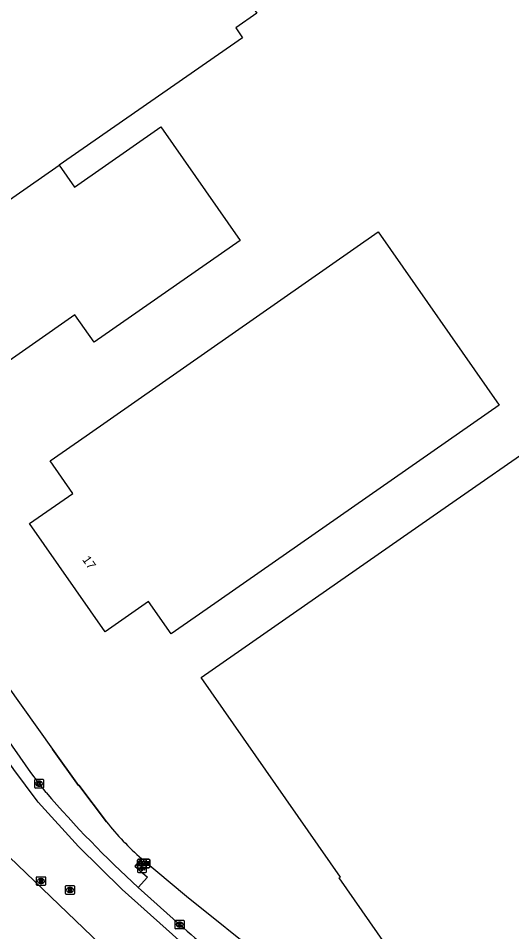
# Model space of a CAD drawing. Extents: x 156651 to 158072, y 387631 to 388990.
# Drawn here: x 157290.6 to 157346.7, y 388103.6 to 388207.5 of the extents above; entities that cross this region are included whole.
import ezdxf

# ---------------------------------------------------------------- set-up
doc = ezdxf.new("R2010")
doc.units = 0
for name, color, linetype in [('IMGEO_Berm_groen', 7, 'Continuous'), ('IMGEO_Hek', 7, 'Continuous'), ('IMGEO_Kolk', 7, 'Continuous'), ('IMGEO_Lichtpunt', 7, 'Continuous'), ('IMGEO_Pand', 7, 'Continuous'), ('IMGEO_Pand_nummerreeks', 7, 'Continuous'), ('IMGEO_Rijbaan_lokaal_gesloten', 7, 'Continuous'), ('IMGEO_Rijbaan_lokaal_open', 7, 'Continuous'), ('IMGEO_Rioolput', 7, 'Continuous'), ('IMGEO_Straatnaambord', 7, 'Continuous'), ('IMGEO_Verklikker', 7, 'Continuous')]:
    doc.layers.add(name, color=color, linetype=linetype)

msp = doc.modelspace()

# ---------------------------------------------------------------- linework, layer by layer
at = {"layer": 'IMGEO_Berm_groen'}
msp.add_lwpolyline([(157304.59, 388111.93), (157309.7, 388107.67), (157345.6, 388078.86), (157350.28, 388079.61), (157353.24, 388083.25)], dxfattribs=at)
at = {"layer": 'IMGEO_Hek'}
for points in [[(157297.47, 388120.3), (157297.41, 388120.27), (157294.46, 388124.39)], [(157300.61, 388116.11), (157297.47, 388120.3)], [(157304.59, 388111.93), (157309.7, 388107.67), (157345.6, 388078.86), (157350.28, 388079.61), (157353.24, 388083.25)]]:
    msp.add_lwpolyline(points, dxfattribs=at)
msp.add_arc((157325.46, 388135.8), 31.7, 218.3759, 228.8332, dxfattribs=at)
at = {"layer": 'IMGEO_Kolk'}
for p, q in [((157292.44, 388120.03), (157292.44, 388120.88)), ((157292.52, 388120.96), (157293.37, 388120.96)), ((157292.93, 388120.74), (157292.96, 388120.74)), ((157293.44, 388120.88), (157293.44, 388120.03)), ((157293.37, 388119.96), (157292.52, 388119.96)), ((157292.95, 388120.18), (157292.93, 388120.18)), ((157308.42, 388104), (157308.42, 388104.85)), ((157308.49, 388104.93), (157309.35, 388104.93)), ((157308.93, 388104.15), (157308.9, 388104.15)), ((157308.91, 388104.71), (157308.93, 388104.71)), ((157309.42, 388104.85), (157309.42, 388104)), ((157309.35, 388103.93), (157308.49, 388103.93))]:
    msp.add_line(p, q, dxfattribs=at)
for points in [[(157292.44, 388120.03), (157292.44, 388120.88)], [(157292.52, 388120.96), (157293.37, 388120.96)], [(157293.44, 388120.88), (157293.44, 388120.03)], [(157293.37, 388119.96), (157292.52, 388119.96)], [(157292.76, 388120.66), (157292.89, 388120.66), (157292.89, 388120.51), (157293.02, 388120.66), (157293.18, 388120.66), (157293.03, 388120.51), (157293.19, 388120.26), (157293.03, 388120.26), (157292.95, 388120.42), (157292.89, 388120.36), (157292.89, 388120.26), (157292.76, 388120.26), (157292.76, 388120.66)], [(157308.42, 388104), (157308.42, 388104.85)], [(157308.49, 388104.93), (157309.35, 388104.93)], [(157308.74, 388104.63), (157308.86, 388104.63), (157308.86, 388104.47), (157308.99, 388104.63), (157309.16, 388104.63), (157309.01, 388104.48), (157309.16, 388104.23), (157309.01, 388104.23), (157308.93, 388104.39), (157308.86, 388104.32), (157308.86, 388104.23), (157308.74, 388104.23), (157308.74, 388104.63)], [(157309.42, 388104.85), (157309.42, 388104)], [(157309.35, 388103.93), (157308.49, 388103.93)]]:
    msp.add_lwpolyline(points, dxfattribs=at)
for centre, start, end in [((157292.52, 388120.88), 91.552, 178.448), ((157292.52, 388120.88), 91.552, 178.448), ((157293.37, 388120.88), 1.552, 88.448), ((157293.37, 388120.88), 1.552, 88.448), ((157292.52, 388120.03), 181.552, 268.448), ((157292.52, 388120.03), 181.552, 268.448), ((157293.37, 388120.03), 271.552, 358.448), ((157293.37, 388120.03), 271.552, 358.448), ((157308.5, 388104.85), 91.552, 178.448), ((157308.5, 388104.85), 91.552, 178.448), ((157309.34, 388104.85), 1.552, 88.448), ((157309.34, 388104.85), 1.552, 88.448), ((157308.5, 388104), 181.552, 268.448), ((157308.5, 388104), 181.552, 268.448), ((157309.34, 388104), 271.552, 358.448), ((157309.34, 388104), 271.552, 358.448)]:
    msp.add_arc(centre, 0.0765, start, end, dxfattribs=at)
for centre, major_axis, ratio, start_param, end_param in [((157292.93, 388120.46), (-0.387, 0.002), 0.722429, 4.712389, 7.853982), ((157292.95, 388120.46), (-0.39, 0.002), 0.717154, 1.570796, 4.712389), ((157308.91, 388104.43), (-0.387, 0.002), 0.722429, 4.712389, 7.853982), ((157308.93, 388104.43), (-0.39, 0.002), 0.717154, 1.570796, 4.712389)]:
    msp.add_ellipse(centre, major_axis=major_axis, ratio=ratio, start_param=start_param, end_param=end_param, dxfattribs=at)
at = {"layer": 'IMGEO_Lichtpunt'}
for p, q in [((157305.05, 388111.35), (157304.24, 388111.35)), ((157305.05, 388111.35), (157304.24, 388111.35)), ((157304.14, 388111.26), (157304.14, 388110.45)), ((157304.14, 388111.26), (157304.14, 388110.45)), ((157304.24, 388110.36), (157305.05, 388110.36)), ((157304.24, 388110.36), (157305.05, 388110.36)), ((157305.14, 388110.45), (157305.14, 388111.26)), ((157305.14, 388110.45), (157305.14, 388111.26))]:
    msp.add_line(p, q, dxfattribs=at)
for points in [[(157304.52, 388110.92), (157304.56, 388110.89), (157304.37, 388110.63), (157304.33, 388110.66), (157304.52, 388110.92)], [(157304.62, 388110.87), (157304.67, 388110.87), (157304.67, 388110.55), (157304.62, 388110.55), (157304.62, 388110.87)], [(157304.73, 388110.89), (157304.77, 388110.92), (157304.96, 388110.66), (157304.92, 388110.63), (157304.73, 388110.89)]]:
    msp.add_lwpolyline(points, dxfattribs=at)
msp.add_circle((157304.64, 388111.06), 0.0994, dxfattribs=at)
for centre, start, end in [((157304.24, 388111.26), 90, 180), ((157304.24, 388111.26), 90, 180), ((157305.05, 388111.26), 0, 90), ((157305.05, 388111.26), 0, 90), ((157304.24, 388110.45), 180, 270), ((157304.24, 388110.45), 180, 270), ((157305.05, 388110.45), 270, 0), ((157305.05, 388110.45), 270, 360)]:
    msp.add_arc(centre, 0.0946, start, end, dxfattribs=at)
at = {"layer": 'IMGEO_Pand'}
for points in [[(157261.99, 388189.49), (157266.09, 388192.36), (157305.78, 388220.06), (157307.1, 388218.17), (157309.5, 388219.83), (157317.68, 388208.11), (157315.29, 388206.44), (157316.06, 388205.33), (157295.22, 388190.82)], [(157295.22, 388190.82), (157296.95, 388188.34), (157306.79, 388195.19), (157315.81, 388182.24), (157299.2, 388170.68), (157297.02, 388173.8), (157287.35, 388167.04), (157283.26, 388164.17), (157277.84, 388168.99)], [(157285.04, 388183.72), (157295.22, 388190.82)], [(157331.5, 388183.23), (157345.24, 388163.54), (157312.05, 388140.36), (157307.95, 388137.49), (157305.37, 388141.18), (157300.46, 388137.75), (157291.86, 388150.06), (157296.77, 388153.49), (157294.19, 388157.18), (157298.29, 388160.04), (157331.5, 388183.23)], [(157351.14, 388160.27), (157367.37, 388137.05), (157375.03, 388126.08), (157374.88, 388125.98), (157371, 388123.28), (157373.93, 388119.07), (157374.29, 388118.55), (157359.45, 388108.2), (157357.92, 388110.39), (157354.88, 388108.29), (157356.43, 388106.06), (157338.38, 388093.47), (157327.06, 388109.73), (157327.2, 388109.84), (157311.35, 388132.54), (157338.61, 388151.54), (157351.14, 388160.27)]]:
    msp.add_lwpolyline(points, dxfattribs=at)
at = {"layer": 'IMGEO_Rijbaan_lokaal_gesloten'}
for points in [[(157341.9, 388076.04), (157340.46, 388076.98), (157309.9, 388101.72), (157302.39, 388108.41), (157297.42, 388113.33), (157292.84, 388118.36), (157292.71, 388118.52), (157290.07, 388122.06), (157284.13, 388130.54), (157250.79, 388178.4), (157218.02, 388225.19), (157168.54, 388296.11), (157166.33, 388299.54), (157165.35, 388302.72), (157165.23, 388304.85), (157165.57, 388307.17), (157166.44, 388309.46), (157166.86, 388310.14)], [(157293.74, 388119.46), (157292, 388121.74), (157285.38, 388131.2)], [(157306.47, 388095.88), (157287.66, 388113.92)], [(157308.92, 388104.43), (157304.2, 388108.65)]]:
    msp.add_lwpolyline(points, dxfattribs=at)
for centre, radius, start, end in [((157390.43, 388202.54), 127.48, 220.6696, 227.4342), ((157412.12, 388221.19), 155.83, 228.5273, 231.9267)]:
    msp.add_arc(centre, radius, start, end, dxfattribs=at)
at = {"layer": 'IMGEO_Rijbaan_lokaal_open'}
for points in [[(157289.3, 388131.62), (157294.46, 388124.39), (157297.41, 388120.27), (157297.47, 388120.3), (157300.61, 388116.11)], [(157304.59, 388111.93), (157303.83, 388111.09), (157305.25, 388109.81), (157304.2, 388108.65)]]:
    msp.add_lwpolyline(points, dxfattribs=at)
msp.add_arc((157325.46, 388135.8), 31.7, 218.3759, 228.8332, dxfattribs=at)
at = {"layer": 'IMGEO_Rioolput'}
for p, q in [((157292.66, 388108.95), (157292.66, 388109.81)), ((157292.74, 388109.88), (157293.59, 388109.88)), ((157293.15, 388109.66), (157293.17, 388109.66)), ((157293.66, 388109.81), (157293.66, 388108.95)), ((157293.59, 388108.88), (157292.74, 388108.88)), ((157293.17, 388109.1), (157293.15, 388109.1)), ((157295.96, 388107.95), (157295.96, 388108.8)), ((157296.03, 388108.87), (157296.88, 388108.87)), ((157296.45, 388108.65), (157296.47, 388108.65)), ((157296.96, 388108.8), (157296.96, 388107.95)), ((157296.88, 388107.87), (157296.03, 388107.87)), ((157296.47, 388108.09), (157296.44, 388108.09))]:
    msp.add_line(p, q, dxfattribs=at)
for points in [[(157292.66, 388108.95), (157292.66, 388109.81)], [(157292.74, 388109.88), (157293.59, 388109.88)], [(157293.25, 388109.58), (157293, 388109.58), (157293, 388109.18)], [(157293, 388109.18), (157293.12, 388109.18), (157293.12, 388109.34), (157293.13, 388109.34)], [(157293.18, 388109.5), (157293.12, 388109.5), (157293.12, 388109.42)], [(157293.12, 388109.42), (157293.17, 388109.42)], [(157293.18, 388109.31), (157293.25, 388109.18), (157293.39, 388109.18), (157293.33, 388109.31)], [(157293.66, 388109.81), (157293.66, 388108.95)], [(157293.59, 388108.88), (157292.74, 388108.88)], [(157295.96, 388107.95), (157295.96, 388108.8)], [(157296.03, 388108.87), (157296.88, 388108.87)], [(157296.55, 388108.57), (157296.29, 388108.57), (157296.29, 388108.17)], [(157296.29, 388108.17), (157296.42, 388108.17), (157296.42, 388108.33), (157296.43, 388108.33)], [(157296.47, 388108.49), (157296.42, 388108.49), (157296.42, 388108.41)], [(157296.42, 388108.41), (157296.47, 388108.41)], [(157296.48, 388108.3), (157296.55, 388108.17), (157296.69, 388108.17), (157296.62, 388108.3)], [(157296.96, 388108.8), (157296.96, 388107.95)], [(157296.88, 388107.87), (157296.03, 388107.87)]]:
    msp.add_lwpolyline(points, dxfattribs=at)
for centre, radius, start, end in [((157292.74, 388109.81), 0.0765, 91.552, 178.448), ((157292.74, 388109.81), 0.0765, 91.552, 178.448), ((157293.13, 388109.29), 0.0533, 26.0293, 88.6989), ((157293.16, 388109.61), 0.19, 274.7715, 282.9687), ((157293.18, 388109.4), 0.0964, 77.0061, 93.1865), ((157293.2, 388109.46), 0.0378, 276.6634, 79.6772), ((157293.25, 388109.47), 0.109, 350.3612, 89.416), ((157293.25, 388109.47), 0.112, 277.5842, 350.9817), ((157293.23, 388109.25), 0.108, 29.5134, 73.7905), ((157293.59, 388109.81), 0.0765, 1.552, 88.448), ((157293.59, 388109.81), 0.0765, 1.552, 88.448), ((157292.74, 388108.96), 0.0765, 181.552, 268.448), ((157292.74, 388108.96), 0.0765, 181.552, 268.448), ((157293.59, 388108.96), 0.0765, 271.552, 358.448), ((157293.59, 388108.96), 0.0765, 271.552, 358.448), ((157296.03, 388108.8), 0.0765, 91.552, 178.448), ((157296.03, 388108.8), 0.0765, 91.552, 178.448), ((157296.43, 388108.28), 0.0533, 26.0293, 88.6989), ((157296.48, 388108.39), 0.0964, 77.0061, 93.1865), ((157296.45, 388108.6), 0.19, 274.7715, 282.9687), ((157296.49, 388108.45), 0.0378, 276.6634, 79.6772), ((157296.55, 388108.46), 0.109, 350.3612, 89.416), ((157296.54, 388108.46), 0.112, 277.5842, 350.9817), ((157296.53, 388108.24), 0.108, 29.5134, 73.7905), ((157296.88, 388108.8), 0.0765, 1.552, 88.448), ((157296.88, 388108.8), 0.0765, 1.552, 88.448), ((157296.03, 388107.95), 0.0765, 181.552, 268.448), ((157296.03, 388107.95), 0.0765, 181.552, 268.448), ((157296.88, 388107.95), 0.0765, 271.552, 358.448), ((157296.88, 388107.95), 0.0765, 271.552, 358.448)]:
    msp.add_arc(centre, radius, start, end, dxfattribs=at)
for centre, major_axis, ratio, start_param, end_param in [((157293.15, 388109.38), (-0.387, 0.002), 0.722429, 4.712389, 7.853982), ((157293.17, 388109.38), (-0.39, 0.002), 0.717154, 1.570796, 4.712389), ((157296.44, 388108.37), (-0.387, 0.002), 0.722429, 4.712389, 7.853982), ((157296.47, 388108.37), (-0.39, 0.002), 0.717154, 1.570796, 4.712389)]:
    msp.add_ellipse(centre, major_axis=major_axis, ratio=ratio, start_param=start_param, end_param=end_param, dxfattribs=at)
at = {"layer": 'IMGEO_Straatnaambord'}
for p, q in [((157304.54, 388110.98), (157304.54, 388111.78)), ((157304.54, 388111.78), (157304.54, 388110.98)), ((157304.64, 388111.88), (157305.43, 388111.88)), ((157305.43, 388111.88), (157304.64, 388111.88)), ((157305.53, 388111.78), (157305.53, 388110.98)), ((157305.53, 388110.98), (157305.53, 388111.78)), ((157305.43, 388110.88), (157304.64, 388110.88)), ((157304.64, 388110.88), (157305.43, 388110.88))]:
    msp.add_line(p, q, dxfattribs=at)
for points in [[(157304.64, 388111.61), (157305.43, 388111.61), (157305.43, 388111.15), (157304.64, 388111.15), (157304.64, 388111.61)], [(157304.71, 388111.55), (157304.71, 388111.21), (157305.37, 388111.21), (157305.37, 388111.55), (157304.71, 388111.55)]]:
    msp.add_lwpolyline(points, dxfattribs=at)
for centre, start, end in [((157304.64, 388111.78), 90, 180), ((157304.64, 388111.78), 90, 180), ((157305.43, 388111.78), 0, 90), ((157305.43, 388111.78), 360, 90), ((157304.64, 388110.98), 180, 270), ((157304.64, 388110.98), 180, 270), ((157305.43, 388110.98), 270, 0), ((157305.43, 388110.98), 270, 0)]:
    msp.add_arc(centre, 0.1, start, end, dxfattribs=at)
at = {"layer": 'IMGEO_Verklikker'}
for p, q in [((157304.14, 388110.96), (157304.14, 388111.76)), ((157304.14, 388111.76), (157304.14, 388110.96)), ((157304.24, 388111.86), (157305.02, 388111.86)), ((157305.02, 388111.86), (157304.24, 388111.86)), ((157305.12, 388111.76), (157305.12, 388110.96)), ((157305.12, 388110.96), (157305.12, 388111.76)), ((157305.02, 388110.86), (157304.24, 388110.86)), ((157304.24, 388110.86), (157305.02, 388110.86))]:
    msp.add_line(p, q, dxfattribs=at)
for points in [[(157304.24, 388111.59), (157305.02, 388111.59), (157305.02, 388111.12), (157304.24, 388111.12), (157304.24, 388111.59)], [(157304.3, 388111.52), (157304.3, 388111.19), (157304.96, 388111.19), (157304.96, 388111.52), (157304.3, 388111.52)]]:
    msp.add_lwpolyline(points, dxfattribs=at)
for centre, start, end in [((157304.24, 388111.76), 90, 180), ((157304.24, 388111.76), 90, 180), ((157305.02, 388111.76), 0, 90), ((157305.02, 388111.76), 360, 90), ((157304.24, 388110.96), 180, 270), ((157304.24, 388110.96), 180, 270), ((157305.02, 388110.96), 270, 0), ((157305.02, 388110.96), 270, 0)]:
    msp.add_arc(centre, 0.1, start, end, dxfattribs=at)

# ---------------------------------------------------------------- texts
at = {"layer": 'IMGEO_Pand_nummerreeks'}
msp.add_text('17', height=1, rotation=304.9442, dxfattribs=at).set_placement((157297.8, 388145.95))

doc.saveas('drawing.dxf')
